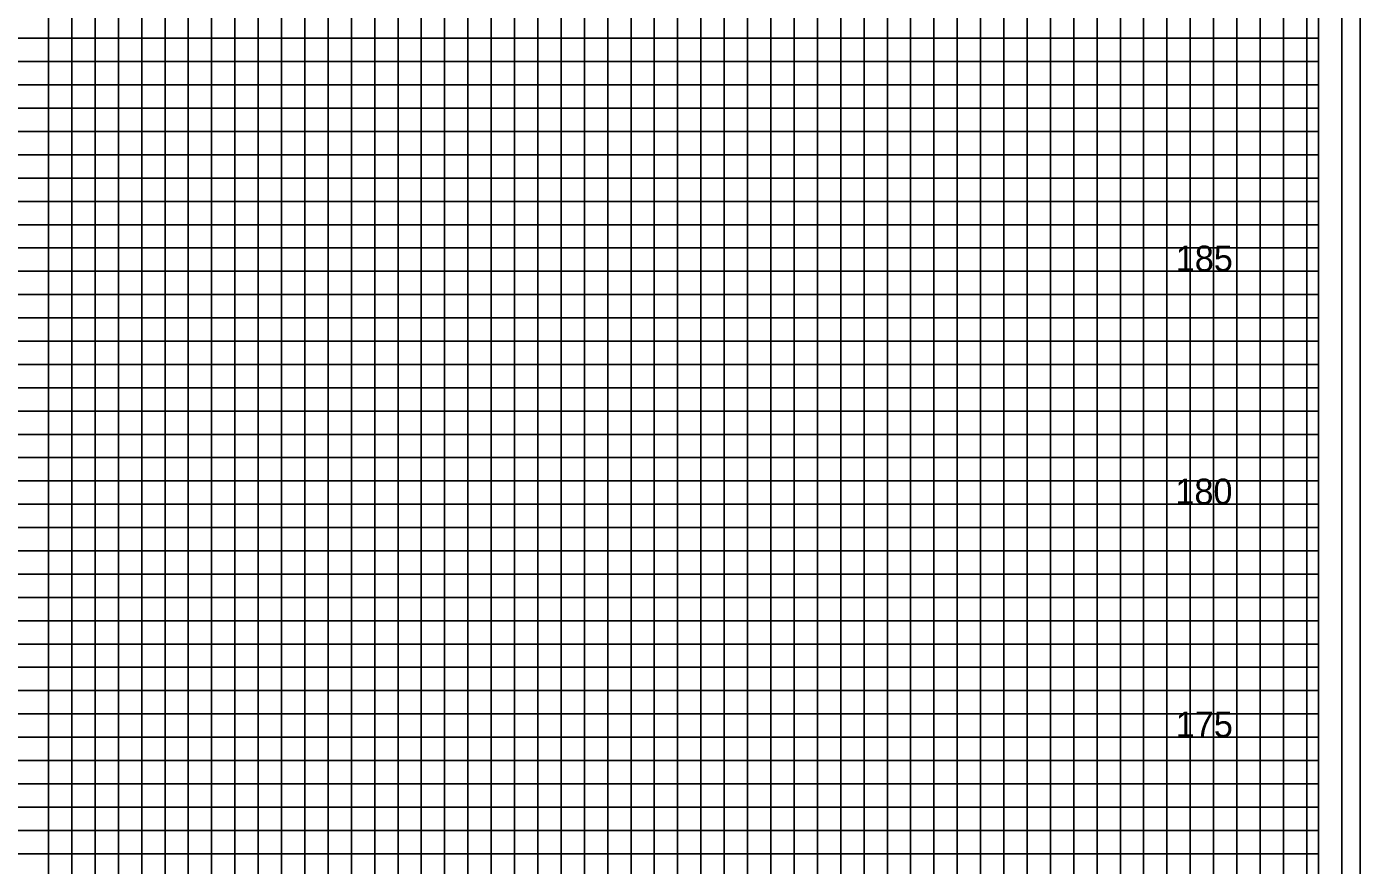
# Model space of a CAD drawing. Extents: x -4 to 103, y -2 to 138.
# Drawn here: x 74.78 to 103.4, y 103.08 to 121.08 of the extents above; entities that cross this region are included whole.
import ezdxf

# ---------------------------------------------------------------- set-up
doc = ezdxf.new("R2010")
doc.units = 0
for name, color, linetype in [('Old_Level_10', 7, 'Continuous'), ('Old_Level_4', 7, 'Continuous'), ('Old_Level_5', 7, 'Continuous'), ('Old_Level_8', 7, 'Continuous'), ('Prop XS Elevation Labels', 7, 'Continuous'), ('Prop XS EOT Tick Mark', 7, 'Continuous'), ('Prop XS Finish Grade', 7, 'Continuous')]:
    doc.layers.add(name, color=color, linetype=linetype)

msp = doc.modelspace()

# ---------------------------------------------------------------- linework, layer by layer
at = {"layer": 'Old_Level_10'}
for p, q in [((91.25, 70.825), (91.25, 134.25)), ((93.75, 70.825), (93.75, 134.25)), ((96.25, 70.825), (96.25, 134.25)), ((98.75, 70.825), (98.75, 134.25)), ((101.25, 70.825), (101.25, 134.25)), ((76.25, 70.825), (76.25, 132.825)), ((78.75, 70.825), (78.75, 132.825)), ((81.25, 70.825), (81.25, 132.825)), ((83.75, 70.825), (83.75, 132.825)), ((86.25, 70.825), (86.25, 132.825)), ((88.75, 70.825), (88.75, 132.825)), ((0, 120.825), (102.5, 120.825)), ((0, 118.325), (102.5, 118.325)), ((0, 115.825), (102.5, 115.825)), ((0, 113.325), (102.5, 113.325)), ((0, 110.825), (102.5, 110.825)), ((0, 108.325), (102.5, 108.325)), ((0, 105.825), (102.5, 105.825)), ((0, 103.325), (102.5, 103.325))]:
    msp.add_line(p, q, dxfattribs=at)
at = {"layer": 'Old_Level_4'}
msp.add_lwpolyline([(103, 136.825), (-2.8, 136.825), (-2.8, 69.825), (103, 69.825)], close=True, dxfattribs=at)
at = {"layer": 'Old_Level_5'}
msp.add_lwpolyline([(103.4, 138.225), (-3.5, 138.225), (-3.5, 68.4), (103.4, 68.4)], close=True, dxfattribs=at)
at = {"layer": 'Old_Level_8'}
for points in [[(91.25, 70.825), (91.25, 134.25), (93.75, 134.25), (93.75, 70.825)], [(96.25, 70.825), (96.25, 134.25), (98.75, 134.25), (98.75, 70.825)], [(101.25, 70.825), (101.25, 134.25)], [(76.25, 70.825), (76.25, 132.825), (78.75, 132.825), (78.75, 70.825)], [(81.25, 70.825), (81.25, 132.825), (83.75, 132.825), (83.75, 70.825)], [(86.25, 70.825), (86.25, 132.825), (88.75, 132.825), (88.75, 70.825)], [(0, 118.325), (102.5, 118.325), (102.5, 120.825), (0, 120.825)], [(0, 113.325), (102.5, 113.325), (102.5, 115.825), (0, 115.825)], [(0, 108.325), (102.5, 108.325), (102.5, 110.825), (0, 110.825)], [(0, 103.325), (102.5, 103.325), (102.5, 105.825), (0, 105.825)]]:
    msp.add_lwpolyline(points, dxfattribs=at)
at = {"layer": 'Prop XS Elevation Labels'}
msp.add_lwpolyline([(102.5, 135.825), (0, 135.825), (0, 70.825), (102.5, 70.825)], close=True, dxfattribs=at)
at = {"layer": 'Prop XS Finish Grade'}
for points in [[(90.25, 70.825), (90.25, 134.25), (90.75, 134.25), (90.75, 70.825)], [(91.75, 70.825), (91.75, 134.25), (92.25, 134.25), (92.25, 70.825)], [(92.75, 70.825), (92.75, 134.25), (93.25, 134.25), (93.25, 70.825)], [(94.25, 70.825), (94.25, 134.25), (94.75, 134.25), (94.75, 70.825)], [(95.25, 70.825), (95.25, 134.25), (95.75, 134.25), (95.75, 70.825)], [(96.75, 70.825), (96.75, 134.25), (97.25, 134.25), (97.25, 70.825)], [(97.75, 70.825), (97.75, 134.25), (98.25, 134.25), (98.25, 70.825)], [(99.25, 70.825), (99.25, 134.25), (99.75, 134.25), (99.75, 70.825)], [(100.25, 70.825), (100.25, 134.25)], [(100.25, 134.25), (100.75, 134.25), (100.75, 70.825), (101.75, 70.825), (101.75, 134.25), (102.25, 134.25), (102.25, 70.825)], [(75.25, 70.825), (75.25, 132.825), (75.75, 132.825), (75.75, 70.825)], [(76.75, 70.825), (76.75, 132.825), (77.25, 132.825), (77.25, 70.825)], [(77.75, 70.825), (77.75, 132.825), (78.25, 132.825), (78.25, 70.825)], [(79.25, 70.825), (79.25, 132.825), (79.75, 132.825), (79.75, 70.825)], [(80.25, 70.825), (80.25, 132.825), (80.75, 132.825), (80.75, 70.825)], [(81.75, 70.825), (81.75, 132.825), (82.25, 132.825), (82.25, 70.825)], [(82.75, 70.825), (82.75, 132.825), (83.25, 132.825), (83.25, 70.825)], [(84.25, 70.825), (84.25, 132.825), (84.75, 132.825), (84.75, 70.825)], [(85.25, 70.825), (85.25, 132.825), (85.75, 132.825), (85.75, 70.825)], [(86.75, 70.825), (86.75, 132.825), (87.25, 132.825), (87.25, 70.825)], [(87.75, 70.825), (87.75, 132.825), (88.25, 132.825), (88.25, 70.825)], [(89.25, 70.825), (89.25, 132.825), (89.75, 132.825), (89.75, 70.825)], [(0, 119.825), (102.5, 119.825), (102.5, 120.325), (0, 120.325)], [(0, 118.825), (102.5, 118.825), (102.5, 119.325), (0, 119.325)], [(0, 117.325), (102.5, 117.325), (102.5, 117.825), (0, 117.825)], [(0, 116.325), (102.5, 116.325), (102.5, 116.825), (0, 116.825)], [(0, 114.825), (102.5, 114.825), (102.5, 115.325), (0, 115.325)], [(0, 113.825), (102.5, 113.825), (102.5, 114.325), (0, 114.325)], [(0, 112.325), (102.5, 112.325), (102.5, 112.825), (0, 112.825)], [(0, 111.325), (102.5, 111.325), (102.5, 111.825), (0, 111.825)], [(0, 109.825), (102.5, 109.825), (102.5, 110.325), (0, 110.325)], [(0, 108.825), (102.5, 108.825), (102.5, 109.325), (0, 109.325)], [(0, 107.325), (102.5, 107.325), (102.5, 107.825), (0, 107.825)], [(0, 106.325), (102.5, 106.325), (102.5, 106.825), (0, 106.825)], [(0, 104.825), (102.5, 104.825), (102.5, 105.325), (0, 105.325)], [(0, 103.825), (102.5, 103.825), (102.5, 104.325), (0, 104.325)]]:
    msp.add_lwpolyline(points, dxfattribs=at)

# ---------------------------------------------------------------- texts
at = {"layer": 'Prop XS EOT Tick Mark'}
for s, p in [('185', (99.438, 115.825)), ('180', (99.43, 110.825)), ('175', (99.438, 105.825))]:
    msp.add_text(s, height=0.55, dxfattribs=at).set_placement(p)

doc.saveas('drawing.dxf')
